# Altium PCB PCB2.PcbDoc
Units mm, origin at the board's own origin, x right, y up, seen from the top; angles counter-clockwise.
Board outline 24.89 x 14.73 mm, 2 copper layers (Top Layer, Bottom Layer); 2 components, 4 nets, 8 pads, 2 vias.
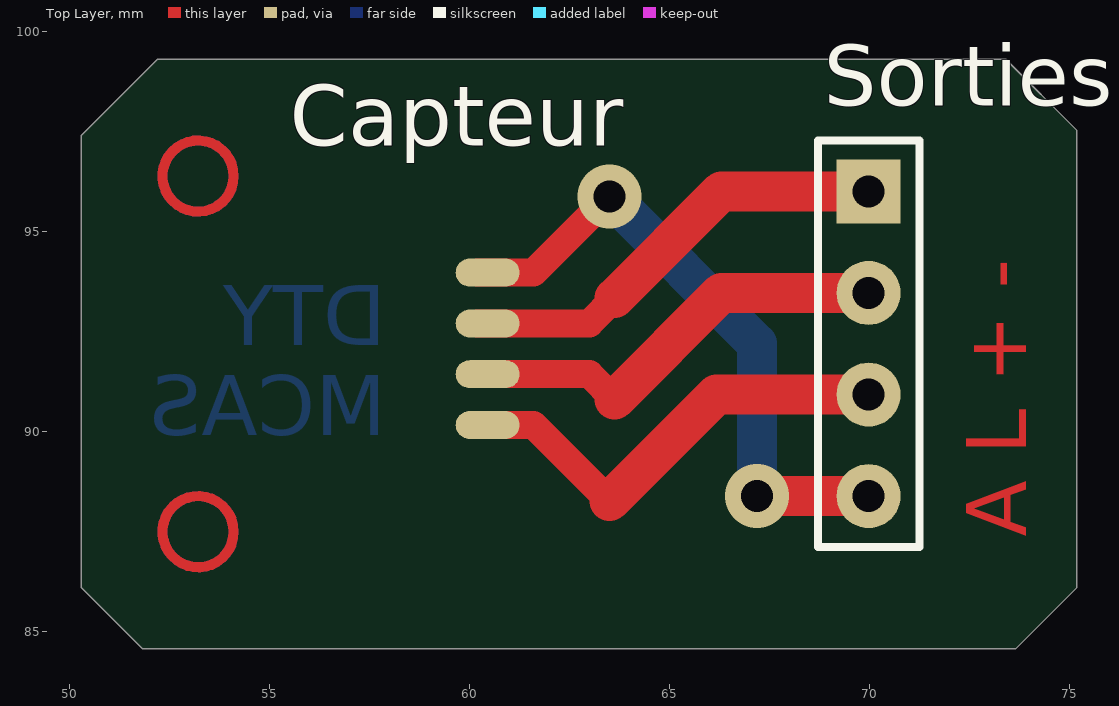
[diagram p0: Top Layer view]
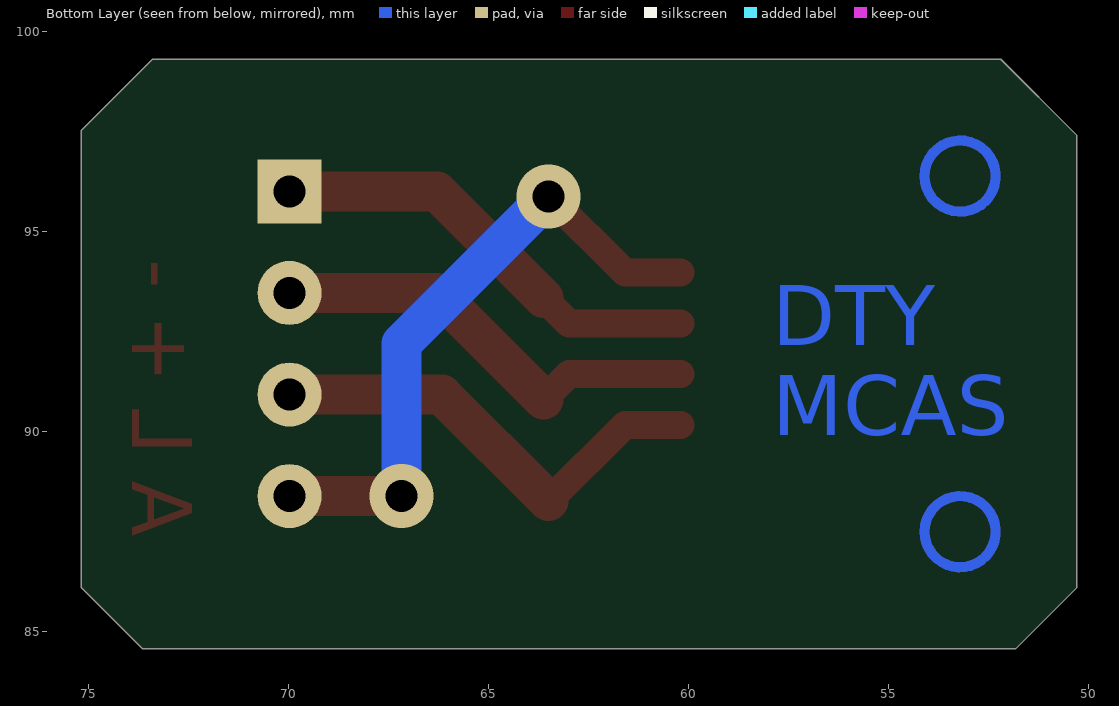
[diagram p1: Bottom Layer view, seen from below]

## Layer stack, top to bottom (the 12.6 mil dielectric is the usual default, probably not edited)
Top Solder: solder mask 0.0102, Solder Resist, Dk 3.5
Top Layer: signal copper 0.0356
Dielectric 1: dielectric 0.32, FR-4, Dk 4.8
Bottom Layer: signal copper 0.0356
Bottom Solder: solder mask 0.0102, Solder Resist, Dk 3.5

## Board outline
51.816,84.582 50.292,86.106 50.292,97.409 52.197,99.314 73.406,99.314 75.184,97.536 75.184,86.106 73.66,84.582

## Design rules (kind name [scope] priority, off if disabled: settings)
Clearance [All] p1: gap=0.254 ignorepadtopadclearanceinfootprint=FALSE except(0: Arc-Hole Track-Hole SMDPad-Hole THPad-Hole Via-Hole Fill-Hole Poly-Hole Region-Hole Text-Hole)
PolygonConnect [All] p1: connectstyle=Relief reliefconductorwidth=0.254 reliefentries=4 polygonreliefangle="90 Angle" airgapwidth=0.254
RoutingVias [All] p1: holewidth=0.711 width=1.27 viastyle="Through Hole" minholewidth=0.711 minwidth=1.27 maxholewidth=0.711 maxwidth=1.27
SolderMaskExpansion [All] p1: expansion=0.102
Width [All] p1: maxlimit=1 minlimit=0.7 preferedwidth=1
30 further rules are at their usual default settings.

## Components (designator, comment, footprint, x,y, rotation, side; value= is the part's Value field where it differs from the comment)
Capteur "Header 4" LUXMETER 60.452,93.98 r180 top
Sorties "Header 4" HDR1X4 69.977,96.012 r270 top

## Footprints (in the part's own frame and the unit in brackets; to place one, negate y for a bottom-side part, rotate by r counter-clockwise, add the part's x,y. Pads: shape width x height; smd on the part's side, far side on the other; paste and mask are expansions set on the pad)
HDR1X4 [mm] "Connector; Header; 4 Position"
  rect 1.6x1.6 hole 0.8: 1(0,0)
  round 1.6 hole 0.8: 2(2.54,0) 3(5.08,0) 4(7.62,0)
  silkscreen extent -1.27,-1.27 8.89,1.27
LUXMETER [mm]
  oval 1.6x0.7 smd: 1(0,0) 2(0,1.27) 3(0,2.54) 4(0,3.81)

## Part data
Capteur Sorties: "Header, 4-Pin"

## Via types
v1: diameter 1.6, hole 0.8, Top Layer to Bottom Layer, 2 vias

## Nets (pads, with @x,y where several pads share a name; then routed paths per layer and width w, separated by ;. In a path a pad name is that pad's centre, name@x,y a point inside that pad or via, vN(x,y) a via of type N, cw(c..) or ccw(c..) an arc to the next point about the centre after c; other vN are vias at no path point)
GND: Capteur.2 Sorties.1 | length 11.1
  Top Layer w0.7: Capteur.2@60.198,92.71 Capteur.2 62.992,92.71 63.627,93.345
  Top Layer w1: 63.627,93.345 66.294,96.012 Sorties.1
SCL: Capteur.4 Sorties.3 | length 11.7
  Top Layer w0.7: Capteur.4@60.198,90.17 Capteur.4 61.595,90.17 63.5,88.265
  Top Layer w1: 63.5,88.265 66.167,90.932 Sorties.3
SDA: Capteur.1 Sorties.4 | length 15.9
  Top Layer w0.7: Capteur.1@60.198,93.98 Capteur.1 61.595,93.98 v1(63.5,95.885)
  Top Layer w1: v1(67.183,88.392) Sorties.4
  Bottom Layer w1: v1(63.5,95.885) 67.183,92.202 v1(67.183,88.392)
VCC: Capteur.3 Sorties.2 | length 11.1
  Top Layer w0.7: Capteur.3@60.198,91.44 Capteur.3 62.992,91.44 63.627,90.805
  Top Layer w1: 63.627,90.805 66.294,93.472 Sorties.2

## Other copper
Top Layer:
  text "A L + -" at 73.914,87.376 h1.5 r90
Bottom Layer:
  text "DTY / MCAS" at 57.912,89.916 h1.5
Multi-Layer:
  circle w0.254: c53.213,87.503 r0.889
  circle w0.254: c53.213,96.393 r0.889

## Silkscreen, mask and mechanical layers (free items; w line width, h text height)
Mechanical 1:
  the board outline again, w0.254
